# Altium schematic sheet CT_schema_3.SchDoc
size 368 x 309 mm
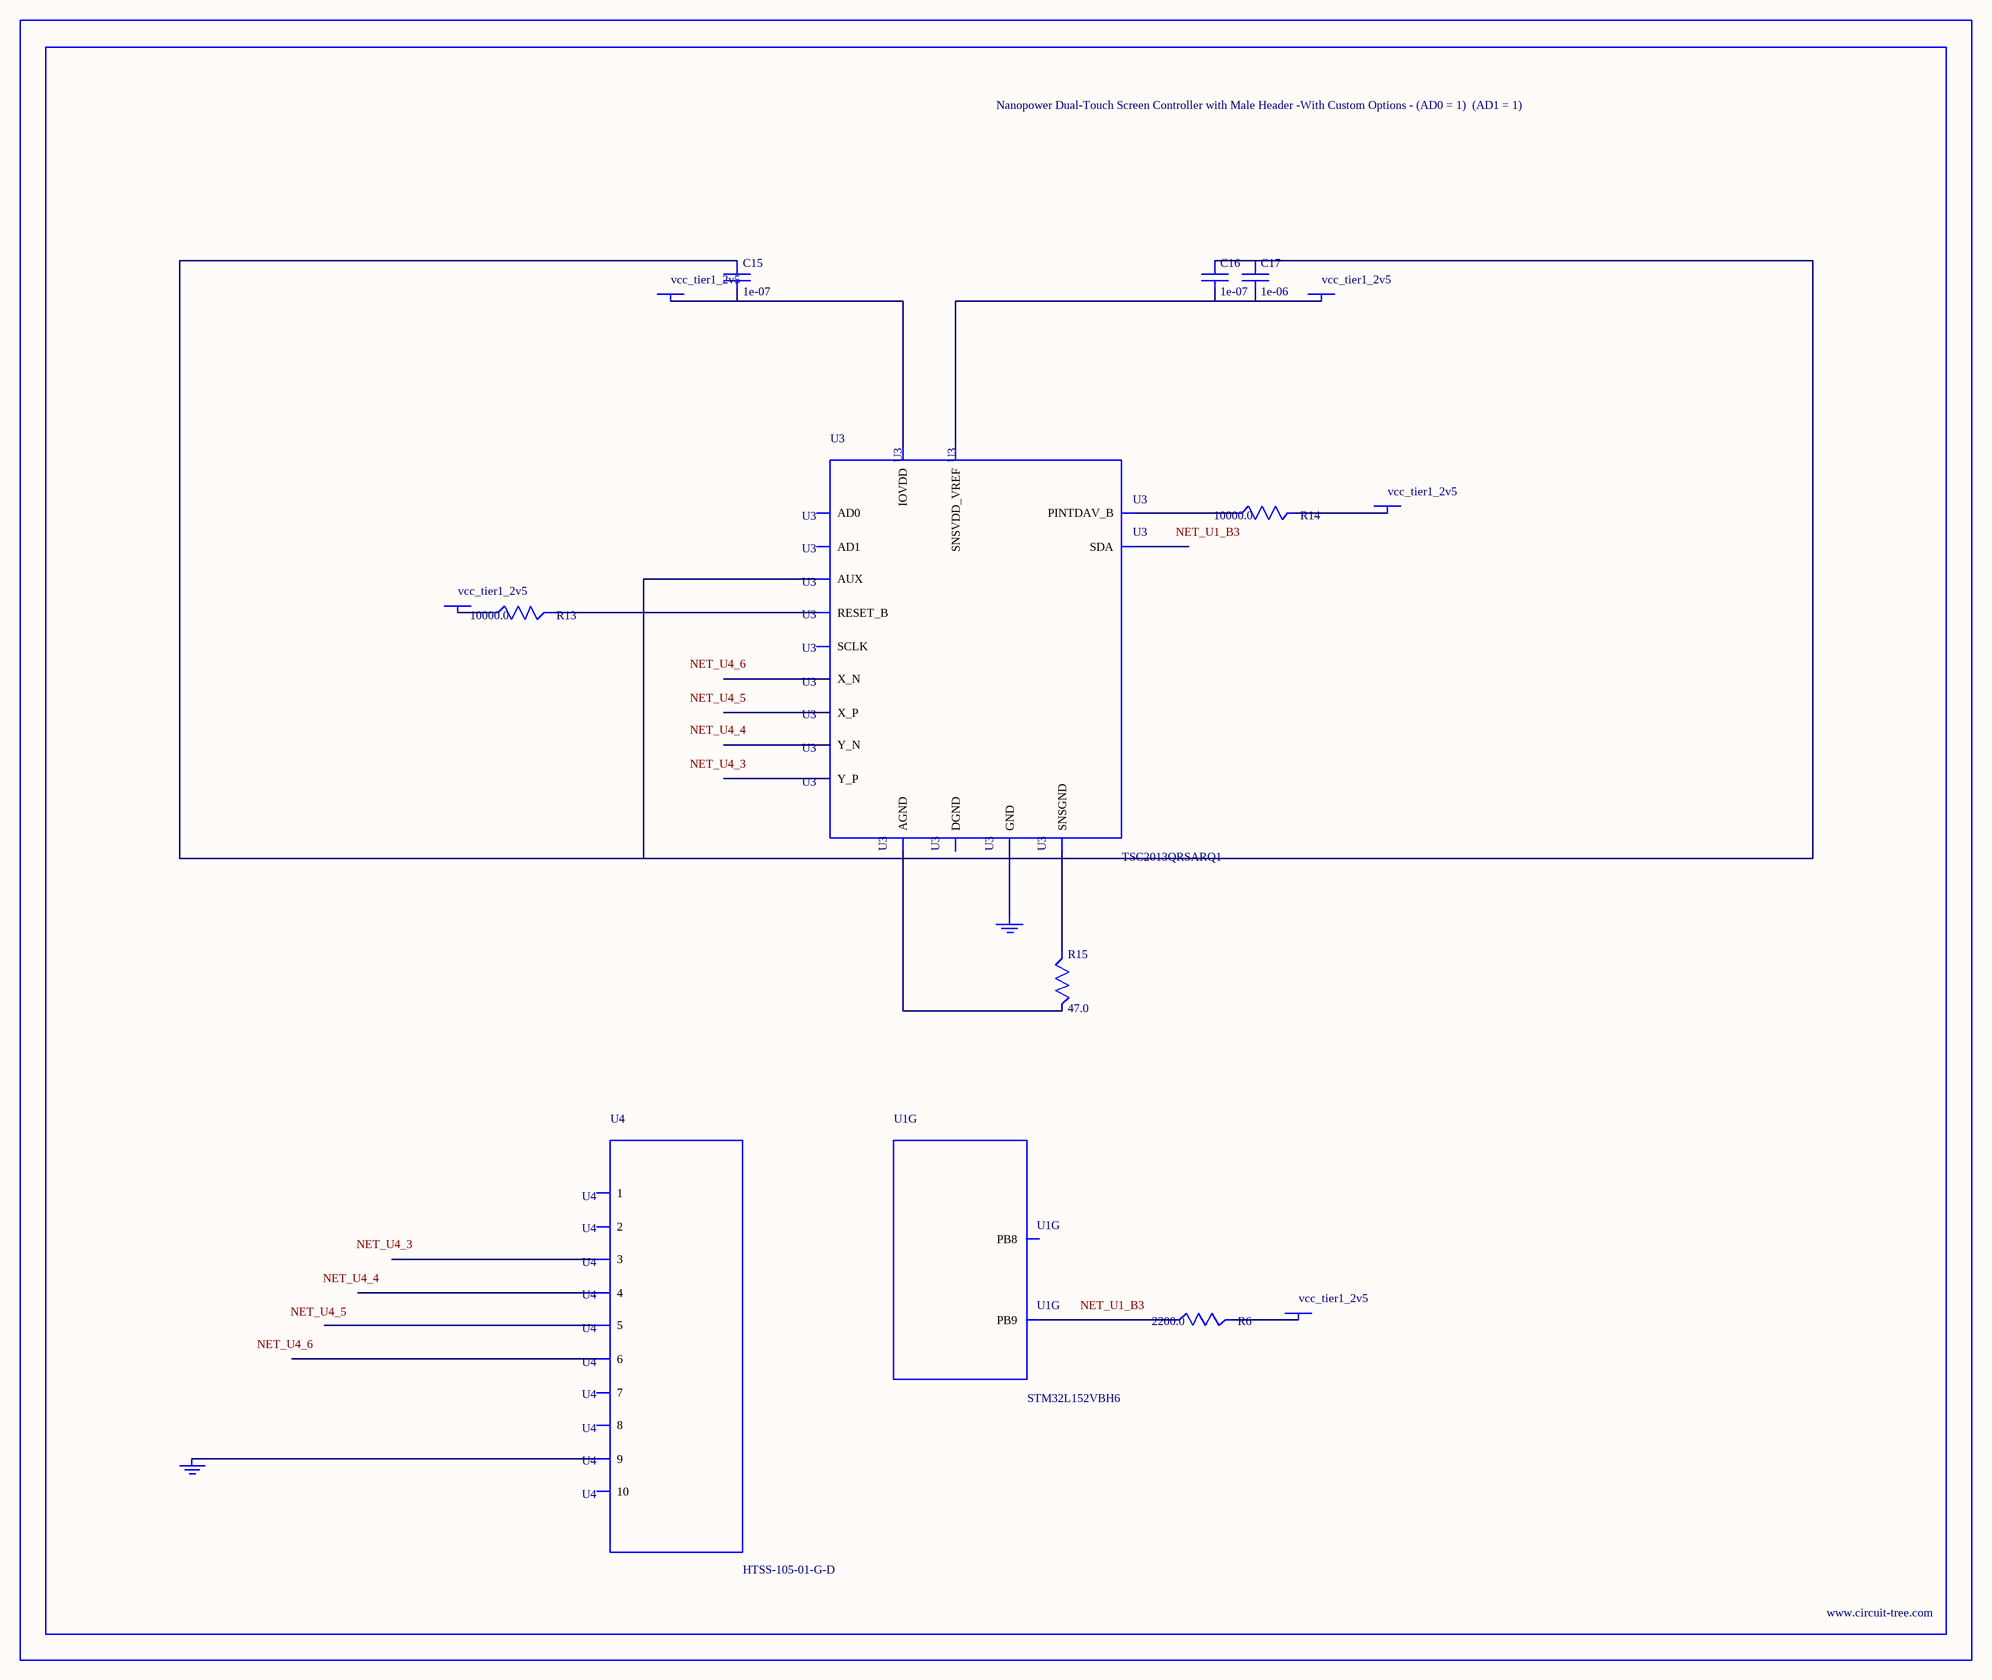
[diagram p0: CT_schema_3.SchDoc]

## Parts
BORDER2  (no value)
C15  1e-07  [C0402]
C16  1e-07  [C0402]
C17  1e-06  [C0603]
GND_INSTANCE_2_0  (no value)
GND_INSTANCE_2_1  (no value)
POWER_INSTANCE_2_0  vcc_tier1_2v5
POWER_INSTANCE_2_1  vcc_tier1_2v5
POWER_INSTANCE_2_2  vcc_tier1_2v5
POWER_INSTANCE_2_3  vcc_tier1_2v5
POWER_INSTANCE_2_4  vcc_tier1_2v5
R6  2200.0  [R0603]
R13  10000.0  [R0603]
R14  10000.0  [R0603]
R15  47.0  [R0603]
U1  STM32L152VBH6  [UFBGA100]  (part G of 9)
U3  TSC2013QRSARQ1  [QFN65P400X400X100-17N]
U4  HTSS-105-01-G-D  [HTSS-105-01-G-D]

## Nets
NetC15_1: C15.1 C16.1 C17.1 R15.1 R15.2 U3.8(AUX) U3.9(AGND) U3.15(SNSGND)
NetC15_2: C15.2 POWER_INSTANCE_2_2.0(PWR) U3.7(IOVDD)
NetC16_2: C16.2 C17.2 POWER_INSTANCE_2_3.0(PWR) U3.10(SNSVDD_VREF)
NetGND_INSTANCE_2_0_0: GND_INSTANCE_2_0.0(GND) U3.17(GND)
NetGND_INSTANCE_2_1_0: GND_INSTANCE_2_1.0(GND) U4.9
NetPOWER_INSTANCE_2_0_0: POWER_INSTANCE_2_0.0(PWR) R14.2
NetPOWER_INSTANCE_2_1_0: POWER_INSTANCE_2_1.0(PWR) R13.1
NetPOWER_INSTANCE_2_4_0: POWER_INSTANCE_2_4.0(PWR) R6.2
NetR6_1: R6.1 U1.B3(PB9)
NetR13_2: R13.2 U3.5(RESET_B)
NetR14_1: R14.1 U3.4(PINTDAV_B)

Not connected (* = marked no-connect by the designer): U1 A3(PB8); U3 1(SDA) 2(SCLK) 3(AD1) 6(DGND) 11(X_P) 12(Y_P) 13(X_N) 14(Y_N) 16(AD0); U4 1 2 3 4 5 6 7 8 10

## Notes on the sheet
- Labels drawn without touching a wire or pin: NET_U1_B3, NET_U4_3, NET_U4_4, NET_U4_5, NET_U4_6

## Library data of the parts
BORDER2 = BORDER_PAGE2
C15 C16 = C0402C104K3RACTU
C17 = C0603C105K3RACTU
GND_INSTANCE_2_0 GND_INSTANCE_2_1 = GND
POWER_INSTANCE_2_0-POWER_INSTANCE_2_4 = PWR
R6 = RC0603JR-072K2L
R13 R14 = RC0603JR-0710KL
R15 = RC0603JR-0747RL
